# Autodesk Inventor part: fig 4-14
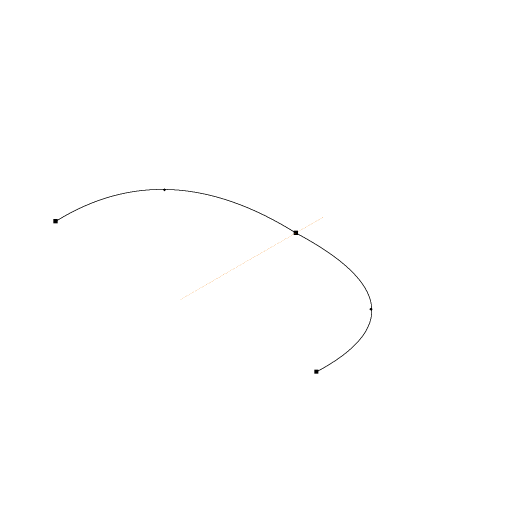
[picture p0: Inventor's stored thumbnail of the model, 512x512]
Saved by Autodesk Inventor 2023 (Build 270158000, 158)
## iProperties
Created: 2012-07
Part Number: fig 4-14
Material: Generic
Document SubType Name: Modeling
Designer: CADCIM
Density: 1 g/cm^3
Appearance: Default
Author: CADCIM
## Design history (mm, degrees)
sketch "Sketch1"
  geometry: L1 (-0.121, 16.232)-(-0.121, 0.498); 5 further points
  constraints: 2 end point, 2 symmetric about line, 1 vertical, 7 other
